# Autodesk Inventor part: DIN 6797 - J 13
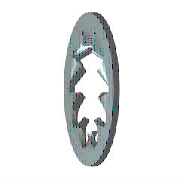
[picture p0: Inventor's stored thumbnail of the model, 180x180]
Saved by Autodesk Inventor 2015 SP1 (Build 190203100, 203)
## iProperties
Created: 2014-02
Part Number: DIN 6797 - J 13
Material: Steel, Mild
Description: Toothed Lock Washer
Document SubType Name: Modeling
Standard: DIN 6797
Designer: Borbon
Standard Revision: 1988
Standards Organization: DIN
Language: en-US
Size Designation: J 13
Categories: <MemberInstance><Categories><Category DisplayName="Fasteners" InternalName="e4da775c-781d-43d5-af7c-5136215cf5a6" Mnemonic="FSTN"><Category DisplayName="Washers
Density: 7.85 g/cm^3
Appearance: Semi-Polished
Mass: 1.21066 g
Surface Area: 4.53541 cm^2
Volume: 0.154224 cm^3
IsCustomPart: 1
Author: Borbon
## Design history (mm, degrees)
sketch "Sketch1"
  geometry: C1 r 10.25 at (0, 0); C2 r 6.5 at (0, 0); 1 further point
  constraints: 2 centre point, 2 coincident
  dimensions: "d0" = 20.5 diameter of C1 (= SD2); "d1" = 13 diameter of C2 (= SD1)
extrude "Body" new body sketch "Sketch1" distance "d2" = 1 (= SD); taper "d3" = 0 deg
sketch "Sketch2"
  geometry: L1 (-1.017, 6.42)-(-1.31, 8.272); L2 (0, 0)-(0, 8.375); L3 (1.017, 6.42)-(1.31, 8.272); L4 (-1.017, 6.42)-(0, 0); L5 (1.017, 6.42)-(0, 0); C1 r 10.25 at (0, 0) reference; A1 r 6.5 centre (0, 0) between (-1.017, 6.42) and (1.017, 6.42) reference; A2 r 8.375 centre (0, 0) between (1.31, 8.272) and (-1.31, 8.272)
  constraints: 10 end point, 5 point on circle, 1 centre point, 1 coincident, 1 collinear, 1 symmetric about line, 1 vertical, 2 other
  dimensions: "d4" = 16.75 diameter of A2 (= 0.5 x SD2 + 0.5 x SD1); "d5" = 9 deg angle of L2 L1 (computed from SAZ)
extrude "Cut" cut sketch "Sketch2" distance "d6" = 1 (= SD); taper "d7" = 0 deg
pattern_circular "Cuts" dims angle "d11" = 360 deg
workplane "Work Plane1"
body "Solid1"
fillet "Fillet1" dims "d8" = 0.39 (= 0.03 x SD1)
other parameters: "SD1" = 13 [user parameter; used in 3 equation terms], "SD2" = 20.5 [user parameter; used in 2 equation terms], "SD" = 1 [user parameter; used in 2 equation terms], "d12" = 0, "d13" = 0, "d18" = 0, "d19" = 0, "NND" = 12 [user parameter]
